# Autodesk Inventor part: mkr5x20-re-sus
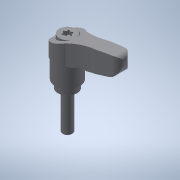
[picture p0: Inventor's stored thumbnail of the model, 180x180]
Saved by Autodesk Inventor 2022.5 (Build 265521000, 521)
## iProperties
Created: 2017-09
Part Number: mkr5x20-re-sus
Material: 一般
Document SubType Name: Modeling
Designer: imaocorp
Density: 1 g/cm^3
Appearance: 既定
Author: imaocorp
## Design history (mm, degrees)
node "mkr5x20-re-sus.x_t1"
node "mkr5x20-re-sus"
node "Base1"
